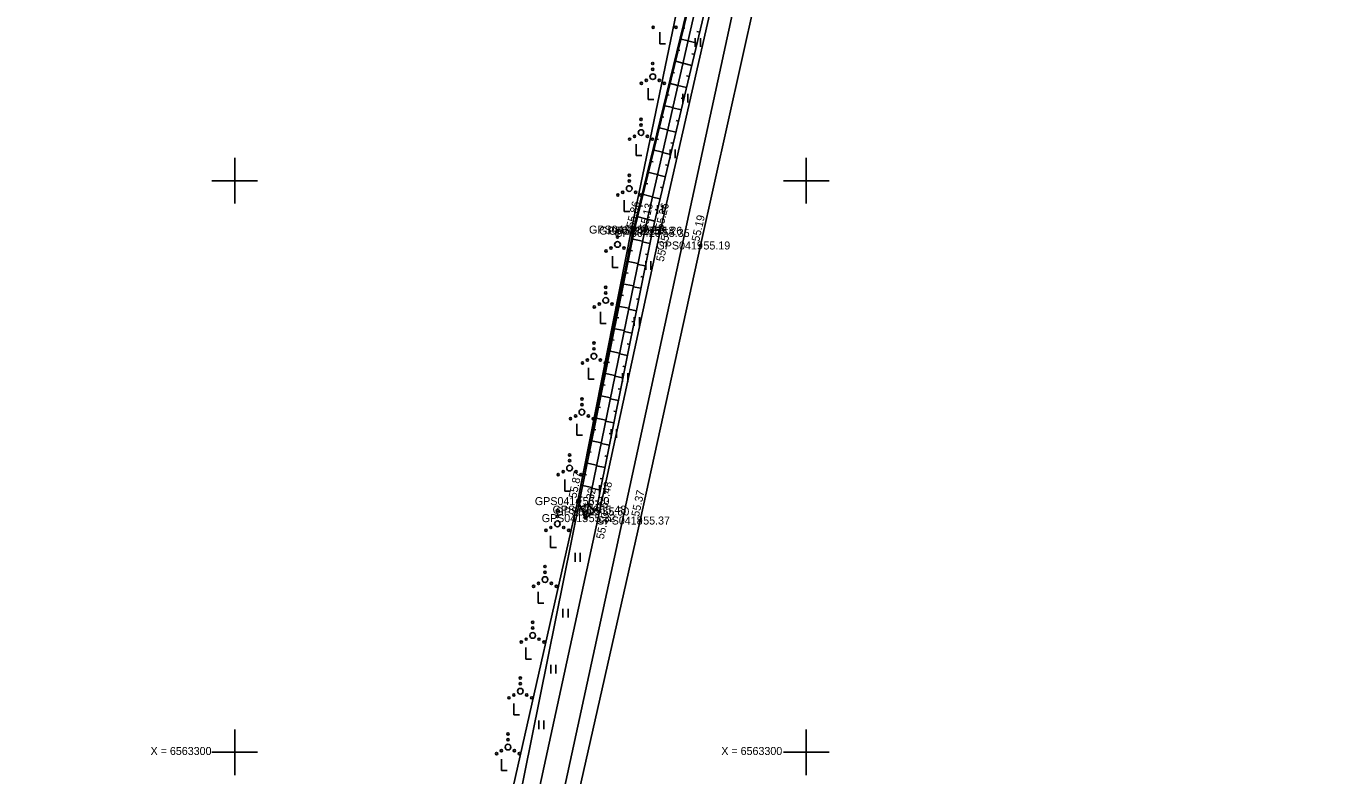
# Model space of a CAD drawing. Extents: x 551623 to 559850, y 6561220 to 6567135.
# Drawn here: x 556681.7 to 556794.9, y 6563298 to 6563363.5 of the extents above; entities that cross this region are included whole.
import ezdxf

# ---------------------------------------------------------------- set-up
doc = ezdxf.new("R2010")
doc.units = 0
for name, color, linetype in [('HALJASTUS', 7, 'Continuous'), ('KORGUS-EH2000', 7, 'Continuous'), ('MOOTKORG-EH2000', 7, 'Continuous'), ('MOOTMPUNKT', 7, 'Continuous'), ('MOOTNR', 7, 'Continuous'), ('MOOTPIIR', 7, 'Continuous'), ('PIIR', 7, 'Continuous'), ('RELJEEF', 7, 'Continuous'), ('TEE', 7, 'Continuous'), ('VORK', 7, 'Continuous')]:
    doc.layers.add(name, color=color, linetype=linetype)

msp = doc.modelspace()

# ---------------------------------------------------------------- linework, layer by layer
at = {"layer": 'HALJASTUS'}
for p, q in [((556737.2, 6563362.98), (556737.2, 6563361.98)), ((556740.3, 6563362.48), (556740.3, 6563361.72)), ((556740.76, 6563362.48), (556740.76, 6563361.72)), ((556737.2, 6563361.98), (556737.7, 6563361.98)), ((556736.16, 6563358.09), (556736.16, 6563357.09)), ((556739.2, 6563357.6), (556739.2, 6563356.84)), ((556739.65, 6563357.6), (556739.65, 6563356.84)), ((556736.16, 6563357.09), (556736.66, 6563357.09)), ((556735.12, 6563353.2), (556735.12, 6563352.2)), ((556735.12, 6563352.2), (556735.62, 6563352.2)), ((556738.09, 6563352.72), (556738.09, 6563351.96)), ((556738.55, 6563352.72), (556738.55, 6563351.96)), ((556734.08, 6563348.3), (556734.08, 6563347.3)), ((556736.99, 6563347.85), (556736.99, 6563347.09)), ((556737.44, 6563347.85), (556737.44, 6563347.09)), ((556734.08, 6563347.3), (556734.58, 6563347.3)), ((556733.04, 6563343.41), (556733.04, 6563342.41)), ((556735.96, 6563342.95), (556735.96, 6563342.19)), ((556736.42, 6563342.95), (556736.42, 6563342.19)), ((556733.04, 6563342.41), (556733.54, 6563342.41)), ((556732, 6563338.52), (556732, 6563337.52)), ((556732, 6563337.52), (556732.5, 6563337.52)), ((556734.95, 6563338.06), (556734.95, 6563337.3)), ((556735.41, 6563338.06), (556735.41, 6563337.3)), ((556730.96, 6563333.63), (556730.96, 6563332.63)), ((556730.96, 6563332.63), (556731.46, 6563332.63)), ((556733.94, 6563333.16), (556733.94, 6563332.4)), ((556734.4, 6563333.16), (556734.4, 6563332.4)), ((556729.92, 6563328.74), (556729.92, 6563327.74)), ((556732.94, 6563328.26), (556732.94, 6563327.5)), ((556733.39, 6563328.26), (556733.39, 6563327.5)), ((556729.92, 6563327.74), (556730.42, 6563327.74)), ((556728.88, 6563323.85), (556728.88, 6563322.85)), ((556728.88, 6563322.85), (556729.38, 6563322.85)), ((556731.93, 6563323.37), (556731.93, 6563322.6)), ((556732.38, 6563323.37), (556732.38, 6563322.6)), ((556727.64, 6563318.92), (556727.64, 6563317.92)), ((556727.64, 6563317.92), (556728.14, 6563317.92)), ((556729.78, 6563317.43), (556729.78, 6563316.67)), ((556730.23, 6563317.43), (556730.23, 6563316.67)), ((556726.56, 6563314.04), (556726.56, 6563313.04)), ((556726.56, 6563313.04), (556727.06, 6563313.04)), ((556728.72, 6563312.54), (556728.72, 6563311.78)), ((556729.17, 6563312.54), (556729.17, 6563311.78)), ((556725.48, 6563309.15), (556725.48, 6563308.15)), ((556725.48, 6563308.15), (556725.98, 6563308.15)), ((556727.66, 6563307.66), (556727.66, 6563306.9)), ((556728.11, 6563307.66), (556728.11, 6563306.9)), ((556724.41, 6563304.27), (556724.41, 6563303.27)), ((556724.41, 6563303.27), (556724.91, 6563303.27)), ((556726.6, 6563302.77), (556726.6, 6563302.01)), ((556727.05, 6563302.77), (556727.05, 6563302.01)), ((556723.33, 6563299.39), (556723.33, 6563298.39)), ((556723.33, 6563298.39), (556723.83, 6563298.39))]:
    msp.add_line(p, q, dxfattribs=at)
msp.add_lwpolyline([(556752.05, 6563429.3), (556753.02, 6563429.04), (556750.97, 6563415.32), (556745.92, 6563393.07), (556740.24, 6563367.29), (556734.99, 6563345.72), (556730.18, 6563321.97), (556724.64, 6563294.5)], dxfattribs=at)
for centre, radius in [((556736.61, 6563363.42), 0.1), ((556738.61, 6563363.42), 0.1), ((556736.58, 6563360.25), 0.1), ((556736.58, 6563359.75), 0.1), ((556736.01, 6563358.77), 0.1), ((556736.58, 6563359.1), 0.25), ((556737.14, 6563358.77), 0.1), ((556735.58, 6563358.52), 0.1), ((556737.58, 6563358.52), 0.1), ((556735.55, 6563355.36), 0.1), ((556735.55, 6563354.21), 0.25), ((556735.55, 6563354.86), 0.1), ((556734.55, 6563353.63), 0.1), ((556734.98, 6563353.88), 0.1), ((556736.11, 6563353.88), 0.1), ((556736.55, 6563353.63), 0.1), ((556734.52, 6563350.46), 0.1), ((556734.52, 6563349.96), 0.1), ((556733.52, 6563348.74), 0.1), ((556733.95, 6563348.99), 0.1), ((556734.52, 6563349.31), 0.25), ((556735.08, 6563348.99), 0.1), ((556735.52, 6563348.74), 0.1), ((556733.49, 6563345.57), 0.1), ((556733.49, 6563345.07), 0.1), ((556732.49, 6563343.85), 0.1), ((556732.92, 6563344.1), 0.1), ((556733.49, 6563344.42), 0.25), ((556734.05, 6563344.1), 0.1), ((556734.49, 6563343.85), 0.1), ((556732.46, 6563340.68), 0.1), ((556732.46, 6563339.53), 0.25), ((556732.46, 6563340.18), 0.1), ((556731.46, 6563338.95), 0.1), ((556731.89, 6563339.2), 0.1), ((556733.02, 6563339.2), 0.1), ((556733.46, 6563338.95), 0.1), ((556731.43, 6563334.64), 0.25), ((556731.43, 6563335.79), 0.1), ((556731.43, 6563335.29), 0.1), ((556730.43, 6563334.06), 0.1), ((556730.86, 6563334.31), 0.1), ((556731.99, 6563334.31), 0.1), ((556732.43, 6563334.06), 0.1), ((556730.38, 6563330.9), 0.1), ((556730.38, 6563330.4), 0.1), ((556729.38, 6563329.17), 0.1), ((556729.82, 6563329.42), 0.1), ((556730.38, 6563329.75), 0.25), ((556730.95, 6563329.42), 0.1), ((556731.38, 6563329.17), 0.1), ((556729.3, 6563326.01), 0.1), ((556729.3, 6563324.86), 0.25), ((556729.3, 6563325.51), 0.1), ((556728.3, 6563324.29), 0.1), ((556728.74, 6563324.54), 0.1), ((556729.87, 6563324.54), 0.1), ((556730.3, 6563324.29), 0.1), ((556728.23, 6563319.98), 0.25), ((556728.23, 6563321.13), 0.1), ((556728.23, 6563320.63), 0.1), ((556727.23, 6563319.41), 0.1), ((556727.66, 6563319.66), 0.1), ((556728.79, 6563319.66), 0.1), ((556729.23, 6563319.41), 0.1), ((556727.15, 6563316.25), 0.1), ((556727.15, 6563315.75), 0.1), ((556726.15, 6563314.52), 0.1), ((556726.58, 6563314.77), 0.1), ((556727.15, 6563315.1), 0.25), ((556727.71, 6563314.77), 0.1), ((556728.15, 6563314.52), 0.1), ((556726.07, 6563311.37), 0.1), ((556725.5, 6563309.89), 0.1), ((556726.07, 6563310.22), 0.25), ((556726.07, 6563310.87), 0.1), ((556726.63, 6563309.89), 0.1), ((556725.07, 6563309.64), 0.1), ((556727.07, 6563309.64), 0.1), ((556724.99, 6563306.49), 0.1), ((556724.99, 6563305.34), 0.25), ((556724.99, 6563305.99), 0.1), ((556723.99, 6563304.76), 0.1), ((556724.42, 6563305.01), 0.1), ((556725.55, 6563305.01), 0.1), ((556725.99, 6563304.76), 0.1), ((556723.91, 6563301.6), 0.1), ((556723.91, 6563301.1), 0.1), ((556722.91, 6563299.88), 0.1), ((556723.34, 6563300.13), 0.1), ((556723.91, 6563300.45), 0.25), ((556724.47, 6563300.13), 0.1), ((556724.91, 6563299.88), 0.1)]:
    msp.add_circle(centre, radius, dxfattribs=at)
at = {"layer": 'KORGUS-EH2000'}
for centre in [(556734.89, 6563345.72), (556735.87, 6563345.63), (556736.55, 6563345.62), (556737.2, 6563345.43), (556740.75, 6563344.33), (556730.03, 6563322.01), (556731.66, 6563321.22), (556730.71, 6563320.48), (556731.92, 6563321.06), (556735.48, 6563320.27)]:
    msp.add_circle(centre, 0.1, dxfattribs=at)
at = {"layer": 'MOOTMPUNKT'}
for centre in [(556734.99, 6563345.72), (556735.87, 6563345.63), (556736.55, 6563345.62), (556737.2, 6563345.43), (556740.75, 6563344.33), (556730.18, 6563321.97), (556731.66, 6563321.22), (556730.71, 6563320.48), (556731.92, 6563321.06), (556735.48, 6563320.27)]:
    msp.add_circle(centre, 0.1, dxfattribs=at)
at = {"layer": 'MOOTPIIR'}
for points in [[(556838.11, 6563834.55), (556835.41, 6563819.71), (556832.84, 6563805.21), (556829.97, 6563791.05), (556817.02, 6563726.91), (556811.4, 6563702.98), (556809.87, 6563694.7), (556802.57, 6563656), (556787.2, 6563585.15), (556769.06, 6563503.89), (556765.06, 6563485.61), (556759.97, 6563461.04), (556756.48, 6563442.49), (556752.05, 6563429.3), (556734.71, 6563345.75), (556730.03, 6563322.01), (556724.17, 6563296.08)], [(556729.29, 6563292.9), (556735.48, 6563320.27), (556740.75, 6563344.33), (556745.53, 6563365.8), (556751.23, 6563392.09), (556755.93, 6563413.85), (556759.83, 6563432.26), (556765.34, 6563459.93), (556770.39, 6563483.2), (556774.26, 6563501.22), (556779.1, 6563523.16), (556783.96, 6563544), (556788.05, 6563560.08), (556792.78, 6563582.54)]]:
    msp.add_lwpolyline(points, dxfattribs=at)
at = {"layer": 'PIIR'}
for points in [[(556692.98, 6563093.02), (556685.3, 6563096.1), (556759.6, 6563438.6), (556879.9, 6563970.48), (556916.82, 6563976.19), (557019.97, 6563895.21), (557017.46, 6563837.28), (557005.87, 6563342.24), (557215.7, 6563357.7), (557240.89, 6563286.87), (557262.52, 6563223.53), (557224.32, 6563129.01), (557161.59, 6562973.57), (557123.42, 6562995.07), (557058.18, 6562998.97)], [(555805.16, 6562850.3), (555826.95, 6563063.64), (555846.51, 6563164.12), (555894.51, 6563325.36), (556136, 6563572.22), (556237.49, 6563672.14), (556288.75, 6563676.33), (556560.07, 6563698.51), (556620.28, 6563801.97), (556702.51, 6563943.25), (556780.4, 6563955.1), (556879.9, 6563970.48), (556759.6, 6563438.6), (556685.3, 6563096.1), (556692.98, 6563093.02), (556667.97, 6562987.78), (556646.18, 6562894.39), (556231.34, 6562873.47), (556132.45, 6562866.66), (555973.8, 6562858.59)]]:
    msp.add_lwpolyline(points, close=True, dxfattribs=at)
at = {"layer": 'RELJEEF'}
for p, q in [((556739.18, 6563363.38), (556739.39, 6563363.33)), ((556738.95, 6563362.41), (556739.66, 6563362.24)), ((556740.45, 6563362.03), (556739.65, 6563362.22)), ((556740.68, 6563363), (556740.44, 6563363.06)), ((556738.71, 6563361.44), (556738.93, 6563361.38)), ((556740.22, 6563361.06), (556739.98, 6563361.11)), ((556738.48, 6563360.47), (556739.21, 6563360.29)), ((556739.98, 6563360.08), (556739.21, 6563360.27)), ((556738.24, 6563359.49), (556738.47, 6563359.44)), ((556739.75, 6563359.11), (556739.52, 6563359.17)), ((556737.77, 6563357.55), (556738, 6563357.49)), ((556738, 6563358.52), (556738.77, 6563358.34)), ((556739.52, 6563358.14), (556738.76, 6563358.32)), ((556737.53, 6563356.58), (556738.32, 6563356.39)), ((556739.06, 6563356.19), (556738.32, 6563356.37)), ((556739.29, 6563357.16), (556739.07, 6563357.22)), ((556737.29, 6563355.61), (556737.54, 6563355.55)), ((556738.83, 6563355.22), (556738.61, 6563355.27)), ((556737.06, 6563354.64), (556737.88, 6563354.44)), ((556738.6, 6563354.25), (556737.88, 6563354.42)), ((556736.82, 6563353.66), (556737.07, 6563353.6)), ((556738.37, 6563353.27), (556738.15, 6563353.32)), ((556736.59, 6563352.69), (556737.43, 6563352.49)), ((556738.14, 6563352.3), (556737.43, 6563352.47)), ((556736.11, 6563350.75), (556736.99, 6563350.54)), ((556736.35, 6563351.72), (556736.61, 6563351.66)), ((556737.91, 6563351.33), (556737.7, 6563351.38)), ((556735.88, 6563349.78), (556736.14, 6563349.71)), ((556737.68, 6563350.35), (556736.99, 6563350.52)), ((556735.64, 6563348.81), (556736.55, 6563348.59)), ((556737.21, 6563348.41), (556736.54, 6563348.57)), ((556737.44, 6563349.38), (556737.24, 6563349.43)), ((556735.4, 6563347.83), (556735.68, 6563347.77)), ((556736.98, 6563347.43), (556736.78, 6563347.48)), ((556735.17, 6563346.86), (556736.1, 6563346.64)), ((556736.75, 6563346.46), (556736.1, 6563346.62)), ((556734.93, 6563345.89), (556735.22, 6563345.82)), ((556736.53, 6563345.49), (556736.33, 6563345.53)), ((556734.52, 6563343.93), (556734.81, 6563343.87)), ((556734.73, 6563344.91), (556735.68, 6563344.72)), ((556736.33, 6563344.51), (556735.67, 6563344.64)), ((556734.32, 6563342.95), (556735.28, 6563342.76)), ((556736.13, 6563343.53), (556735.93, 6563343.57)), ((556734.12, 6563341.97), (556734.41, 6563341.91)), ((556735.94, 6563342.55), (556735.27, 6563342.68)), ((556733.92, 6563340.99), (556734.88, 6563340.8)), ((556735.54, 6563340.59), (556734.86, 6563340.72)), ((556735.74, 6563341.57), (556735.54, 6563341.61)), ((556733.72, 6563340.01), (556734.01, 6563339.96)), ((556735.35, 6563339.61), (556735.14, 6563339.65)), ((556733.52, 6563339.03), (556734.48, 6563338.84)), ((556735.15, 6563338.62), (556734.46, 6563338.76)), ((556733.32, 6563338.05), (556733.61, 6563338)), ((556734.95, 6563337.64), (556734.75, 6563337.69)), ((556732.92, 6563336.1), (556733.2, 6563336.04)), ((556733.12, 6563337.07), (556734.07, 6563336.88)), ((556734.76, 6563336.66), (556734.06, 6563336.8)), ((556732.72, 6563335.12), (556733.67, 6563334.92)), ((556734.56, 6563335.68), (556734.35, 6563335.73)), ((556732.52, 6563334.14), (556732.8, 6563334.08)), ((556734.36, 6563334.7), (556733.66, 6563334.84)), ((556734.17, 6563333.72), (556733.95, 6563333.76)), ((556732.32, 6563333.16), (556733.27, 6563332.96)), ((556733.97, 6563332.74), (556733.25, 6563332.89)), ((556732.11, 6563332.18), (556732.4, 6563332.12)), ((556733.77, 6563331.76), (556733.56, 6563331.8)), ((556731.91, 6563331.2), (556732.87, 6563331)), ((556733.58, 6563330.78), (556732.85, 6563330.93)), ((556731.51, 6563329.24), (556732.47, 6563329.04)), ((556731.71, 6563330.22), (556732, 6563330.16)), ((556733.38, 6563329.8), (556733.16, 6563329.84)), ((556731.31, 6563328.26), (556731.6, 6563328.2)), ((556733.18, 6563328.82), (556732.45, 6563328.97)), ((556731.11, 6563327.28), (556732.06, 6563327.08)), ((556732.79, 6563326.86), (556732.05, 6563327.01)), ((556732.99, 6563327.84), (556732.77, 6563327.88)), ((556730.91, 6563326.3), (556731.2, 6563326.24)), ((556732.59, 6563325.88), (556732.37, 6563325.92)), ((556730.71, 6563325.32), (556731.66, 6563325.12)), ((556732.4, 6563324.9), (556731.65, 6563325.05)), ((556730.51, 6563324.34), (556730.79, 6563324.28)), ((556732.2, 6563323.92), (556731.97, 6563323.96)), ((556730.31, 6563323.36), (556731.26, 6563323.17)), ((556732, 6563322.94), (556731.24, 6563323.09)), ((556730.11, 6563322.38), (556730.39, 6563322.32)), ((556730.29, 6563321.44), (556730.97, 6563321.74)), ((556731.46, 6563321.07), (556730.96, 6563321.71)), ((556731.81, 6563321.96), (556731.58, 6563322)), ((556730.69, 6563320.53), (556730.7, 6563320.53))]:
    msp.add_line(p, q, dxfattribs=at)
for points in [[(556788.59, 6563584.23), (556783.65, 6563561.56), (556779.99, 6563544.9), (556774.7, 6563524.07), (556769.69, 6563502.72), (556765.66, 6563484.53), (556760.96, 6563460.73), (556757.31, 6563442.67), (556755.33, 6563433.04), (556751.45, 6563415.04), (556746.99, 6563393.43), (556740.78, 6563367.15), (556735.87, 6563345.63), (556730.71, 6563320.48)], [(556755.97, 6563432.99), (556752.15, 6563414.93), (556747.69, 6563393.32), (556741.59, 6563366.87), (556736.55, 6563345.62), (556731.66, 6563321.22), (556730.71, 6563320.48), (556730.03, 6563322.01), (556734.89, 6563345.72), (556740.14, 6563367.29), (556745.82, 6563393.07), (556750.87, 6563415.32), (556754.08, 6563432.88)]]:
    msp.add_lwpolyline(points, dxfattribs=at)
at = {"layer": 'TEE'}
for points in [[(556789.65, 6563583.8), (556784.53, 6563561.18), (556780.77, 6563544.63), (556775.84, 6563524.15), (556770.72, 6563502.37), (556766.84, 6563484.07), (556762.2, 6563460.74), (556758.47, 6563442.44), (556756.4, 6563432.89), (556752.55, 6563414.74), (556748.02, 6563393.01), (556742.03, 6563366.72), (556737.2, 6563345.43), (556731.92, 6563321.06), (556725.97, 6563293.68)], [(556792.78, 6563582.54), (556788.05, 6563560.08), (556783.96, 6563544), (556779.1, 6563523.16), (556774.26, 6563501.22), (556770.39, 6563483.2), (556765.34, 6563459.93), (556761.87, 6563441.55), (556759.83, 6563432.26), (556755.93, 6563413.85), (556751.23, 6563392.09), (556745.53, 6563365.8), (556740.75, 6563344.33), (556735.48, 6563320.27), (556729.29, 6563292.9)]]:
    msp.add_lwpolyline(points, dxfattribs=at)
at = {"layer": 'VORK'}
for p, q in [((556700, 6563352), (556700, 6563348)), ((556750, 6563352), (556750, 6563348)), ((556698, 6563350), (556702, 6563350)), ((556748, 6563350), (556752, 6563350)), ((556700, 6563302), (556700, 6563298)), ((556750, 6563302), (556750, 6563298)), ((556698, 6563300), (556702, 6563300)), ((556748, 6563300), (556752, 6563300))]:
    msp.add_line(p, q, dxfattribs=at)

# ---------------------------------------------------------------- texts
at = {"layer": 'KORGUS-EH2000'}
for s, rotation, p in [('55.86', 76.3348, (556734.92, 6563345.83)), (' 55.13', 77.152, (556736.02, 6563345.4)), (' 55.26', 76.6521, (556737.4, 6563345.42)), (' 55.19', 77.4512, (556740.58, 6563344.37)), (' 55.35', 77.7579, (556737.48, 6563342.62)), ('55.87', 78.4162, (556729.89, 6563322.18)), (' 55.48', 78.6594, (556732.52, 6563321.05)), (' 55.32', 78.4004, (556731.09, 6563320.49)), (' 55.37', 77.6316, (556735.31, 6563320.31)), (' 55.50', 77.7467, (556732.23, 6563318.34))]:
    msp.add_text(s, height=0.7, rotation=rotation, dxfattribs=at).set_placement(p)
at = {"layer": 'MOOTKORG-EH2000'}
for s, p in [(' 55.19', (556734.99, 6563345.37)), (' 55.13', (556735.87, 6563345.28)), (' 55.26', (556736.55, 6563345.27)), (' 55.35', (556737.2, 6563345.08)), (' 55.19', (556740.75, 6563343.98)), (' 55.20', (556730.18, 6563321.62)), (' 55.48', (556731.66, 6563320.87)), (' 55.50', (556731.92, 6563320.71)), (' 55.32', (556730.71, 6563320.13)), (' 55.37', (556735.48, 6563319.92))]:
    msp.add_text(s, height=0.7, dxfattribs=at).set_placement(p)
at = {"layer": 'MOOTNR'}
for s, p in [('GPS0423 ', (556731, 6563345.37)), ('GPS0422 ', (556731.88, 6563345.28)), ('GPS0421 ', (556732.7, 6563345.27)), ('GPS0420 ', (556733.21, 6563345.08)), ('GPS0419 ', (556736.9, 6563343.98)), ('GPS0414 ', (556726.26, 6563321.62)), ('GPS0416 ', (556727.81, 6563320.87)), ('GPS0417 ', (556728.07, 6563320.71)), ('GPS0415 ', (556726.86, 6563320.13)), ('GPS0418 ', (556731.63, 6563319.92))]:
    msp.add_text(s, height=0.7, dxfattribs=at).set_placement(p)
at = {"layer": 'VORK'}
for p in [(556692.64, 6563299.76), (556742.57, 6563299.76)]:
    msp.add_text('X = 6563300', height=0.7, dxfattribs=at).set_placement(p)

doc.saveas('drawing.dxf')
